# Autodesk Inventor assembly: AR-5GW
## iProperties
Shininess: 64.0
Length Units: 11269
Angle Units: 11279
Time Units: 11290
Mass Units: 11284
Length Display Precision: 2
Angle Display Precision: 1
Created: 2002-02
Part Number: AR-5GW
Document SubType Name: ｱｾﾝﾌﾞﾘ
Designer: Administrator
Density: 0.0
Volumn: 0.0
Area: 0.0
PropertySet Name: Model Information
Control State: 0
Master: False
Checked Out: False
d63: 0.00 mm
Author: Administrator
